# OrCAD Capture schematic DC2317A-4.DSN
size B; title: HIGH EFFICIENCY 4 PHASE 120A; rev: 4; company: TM
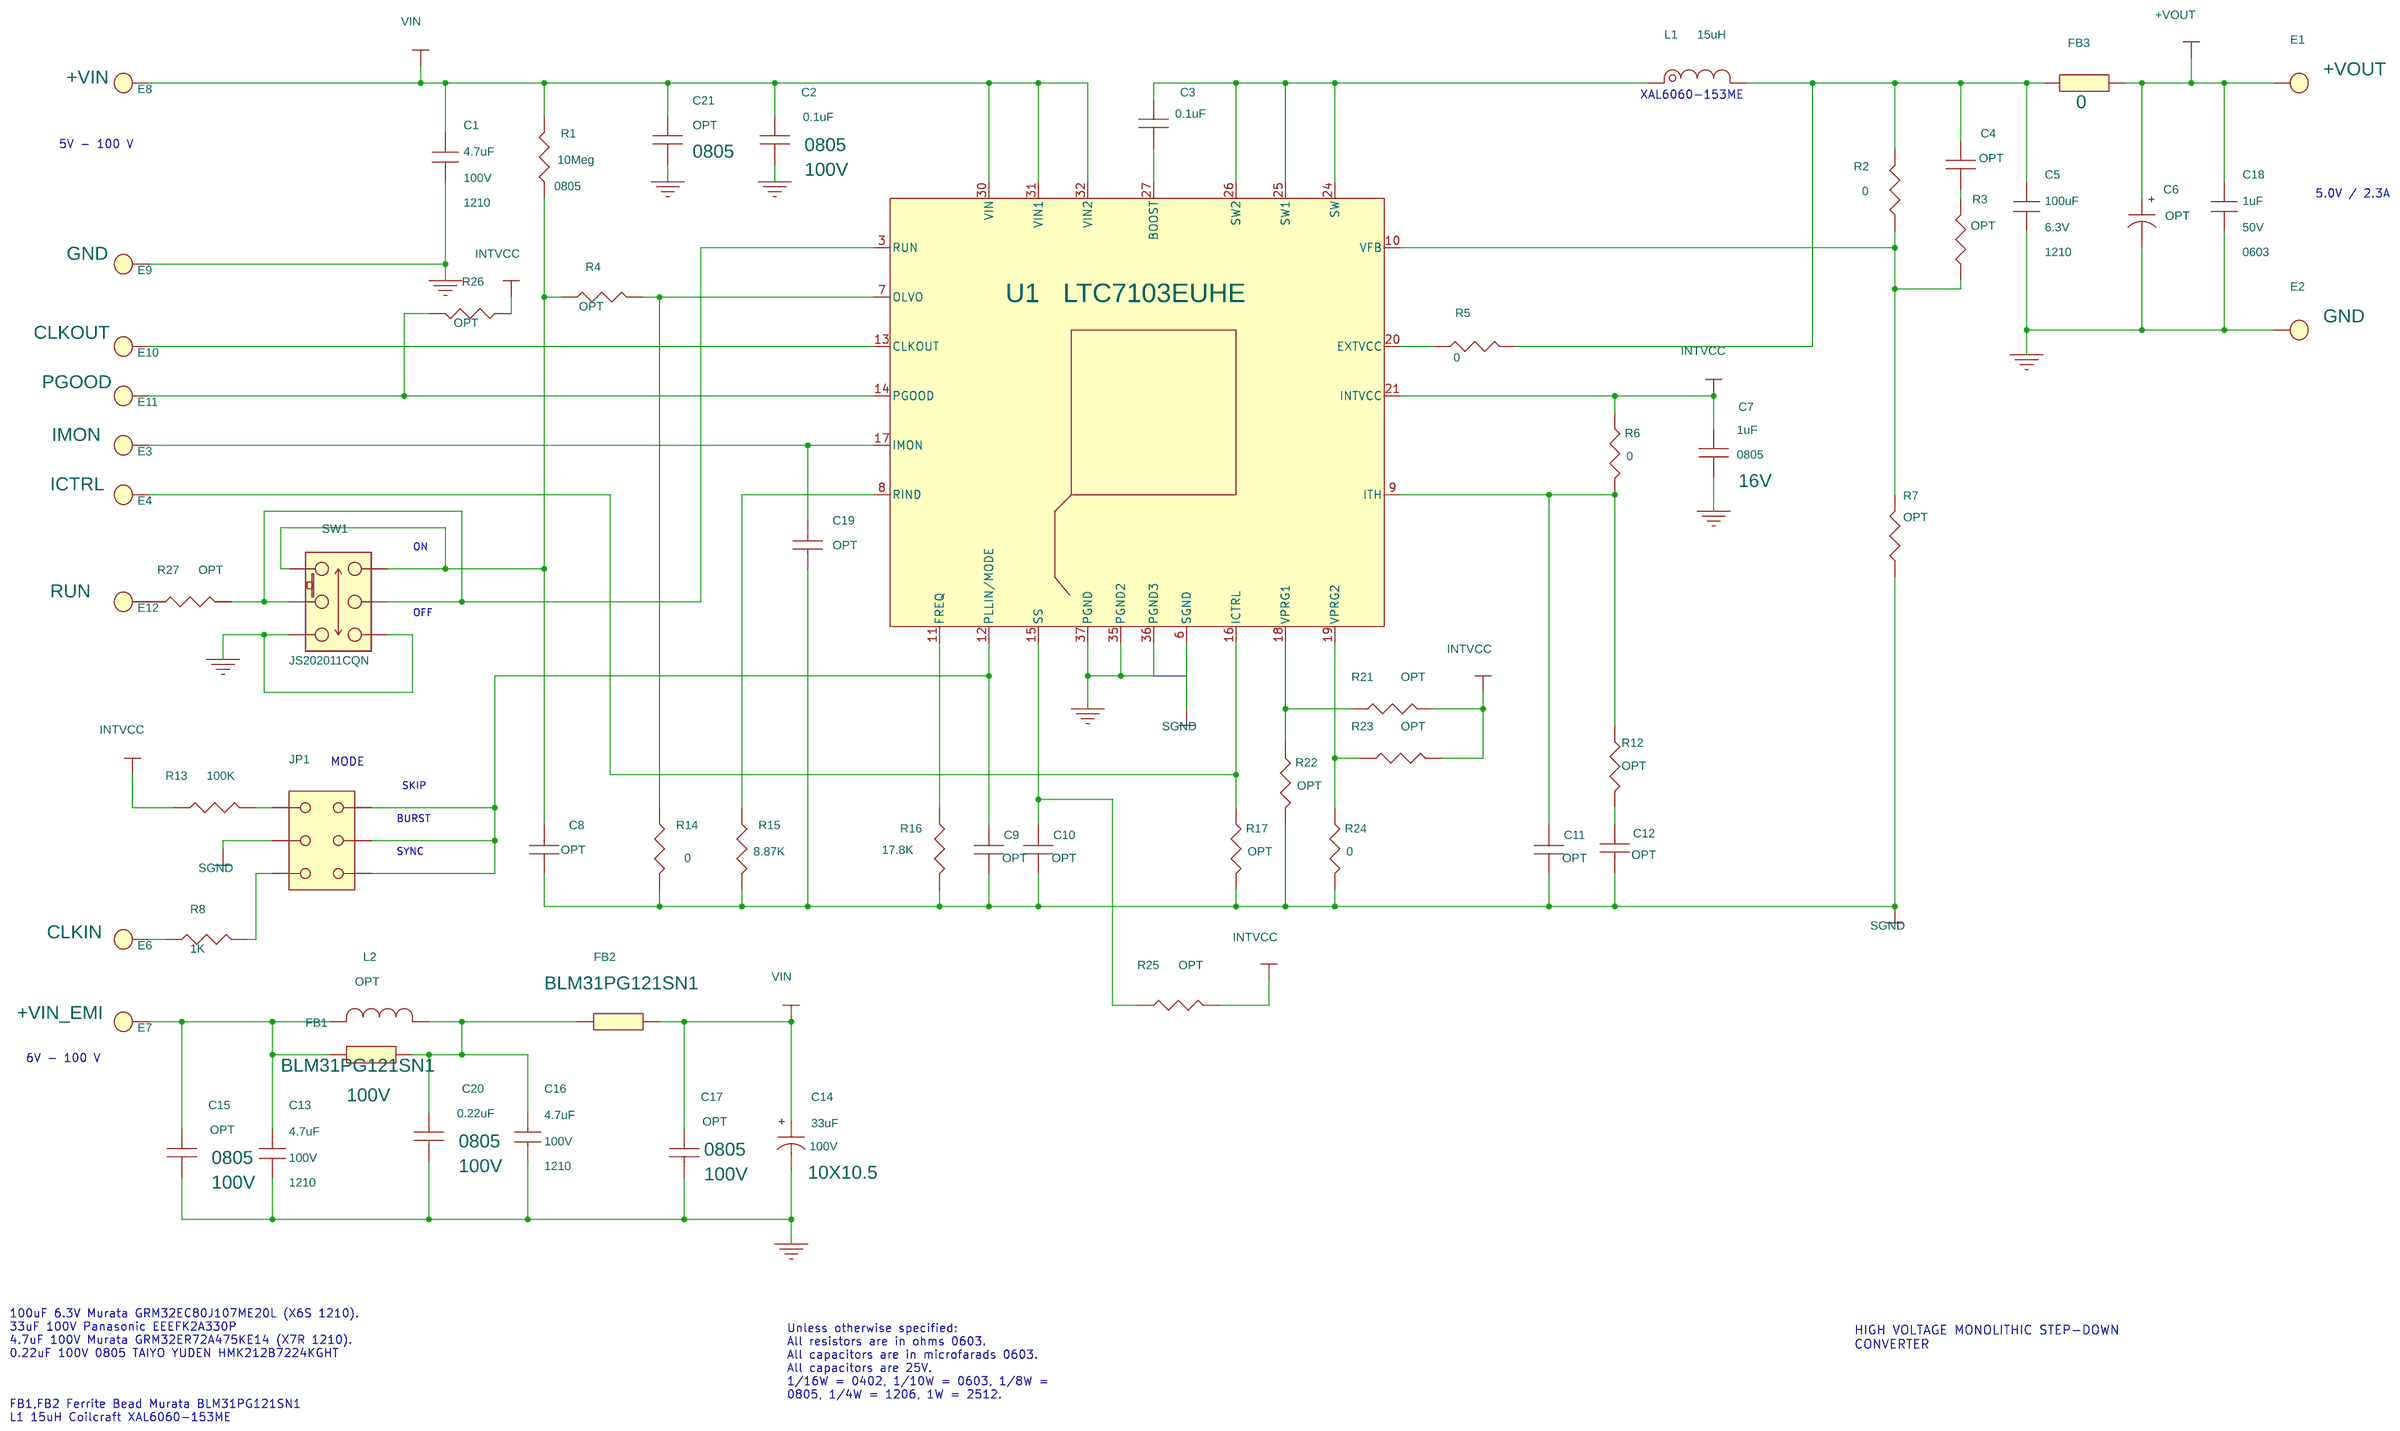
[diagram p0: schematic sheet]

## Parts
C1  4.7uF  [1210]
C2  0.1uF  [0805]
C3  0.1uF  [0603]
C4  OPT  [0603]
C5  100uF  [1210]
C6  OPT  [7343]
C7  1uF  [0805]
C8  OPT  [0805]
C9  OPT  [0603]
C10  OPT  [0603]
C11  OPT  [0603]
C12  OPT  [0603]
C13  4.7uF  [1210]
C14  33uF  [SANYO-10.3X10.3]
C15  OPT  [0805]
C16  4.7uF  [1210]
C17  OPT  [0805]
C18  1uF  [0603]
C19  OPT  [0603]
C20  0.22uF  [0805]
C21  OPT  [0805]
E1  TURRET-23  [pad150-095]
E2  TURRET-23  [pad150-095]
E3  TURRET-23  [pad150-095]
E4  TURRET-23  [pad150-095]
E6  TURRET-23  [pad150-095]
E7  TURRET-23  [pad150-095]
E8  TURRET-23  [pad150-095]
E9  TURRET-23  [pad150-095]
E10  TURRET-23  [pad150-095]
E11  TURRET-23  [pad150-095]
E12  TURRET-23  [pad150-095]
FB1  BLM31PG121SN1  [1206]
FB2  BLM31PG121SN1  [1206]
FB3  0  [1206]
JP1  Voltage Select  [JP2X3/079]
L1  15uH  [XAL6060]
L2  OPT  [IHLP-1616]
R1  10Meg  [0805]
R2  0  [0603]
R3  OPT  [0603]
R4  OPT  [0805]
R5  0  [0603]
R6  0  [0603]
R7  OPT  [0603]
R8  1K  [0603]
R12  OPT  [0603]
R13  100K  [0603]
R14  0  [0603]
R15  8.87K  [0603]
R16  17.8K  [0603]
R17  OPT  [0603]
R21  OPT  [0603]
R22  OPT  [0603]
R23  OPT  [0603]
R24  0  [0603]
R25  OPT  [0603]
R26  OPT  [0603]
R27  OPT  [0603]
SW1  JS202011CQN  [JS202011]
U1  LTC7103EUHE  [UHE_36_QFN_5MMX6MM]
XJP2  2mm Ctrs.

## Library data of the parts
C1 C13 C16 = CAP1210: 1ST PART FIELD: 100V; 2ND PART FIELD: 20%, 1210; 3RD PART FIELD: X7R; 4TH PART FIELD: TDK; 7TH PART FIELD: CAP.
C2 C15 C17 C20 C21 = 12061C104KAT2A_0: 1ST PART FIELD: 100V; 2ND PART FIELD: 10%, 0805; 3RD PART FIELD: X7R; 4TH PART FIELD: AVX; 7TH PART FIELD: CAP.
C3 = 12061C104KAT2A_0: 1ST PART FIELD: 25V; 2ND PART FIELD: 10%, 0805; 3RD PART FIELD: X7R; 4TH PART FIELD: AVX; 5TH PART FIELD: 0805; 7TH PART FIELD: CAP.
C4 = 12061C104KAT2A_0: 1ST PART FIELD: 25V; 2ND PART FIELD: 10%, 0603; 3RD PART FIELD: NPO; 4TH PART FIELD: AVX; 5TH PART FIELD: 06033A680KAT2A; 7TH PART FIELD: CAP.
C5 = CAP1210: 1ST PART FIELD: 6.3V; 2ND PART FIELD: 20%, 1210; 3RD PART FIELD: X7R; 4TH PART FIELD: TDK; 7TH PART FIELD: CAP.
C6 = CAP+7343: 1ST PART FIELD: 16V
C7 = TMK316BJ105KL: 1ST PART FIELD: 16V; 2ND PART FIELD: 10%, 0805; 3RD PART FIELD: X7R; 4TH PART FIELD: TAIYO TUDEN; 7TH PART FIELD: CAP.
C8-C11 C19 = 12061C104KAT2A_0: 1ST PART FIELD: 25V; 2ND PART FIELD: 10%, 0603; 3RD PART FIELD: NPO; 4TH PART FIELD: AVX; 5TH PART FIELD: 06033A471KAT2A; 7TH PART FIELD: CAP.
C12 = 12061C104KAT2A_0: 1ST PART FIELD: 25V; 2ND PART FIELD: 10%, 0603; 3RD PART FIELD: X7R; 4TH PART FIELD: AVX; 5TH PART FIELD: 06033C103KAT2A; 7TH PART FIELD: CAP.
C14 = CAP-HVH-10X10.5: 1ST PART FIELD: 100V; 5TH PART FIELD: 10X10.5
C18 = CAP1210: 1ST PART FIELD: 50V; 2ND PART FIELD: 20%, 1210; 3RD PART FIELD: X7R; 4TH PART FIELD: TDK; 5TH PART FIELD: 1210; 7TH PART FIELD: CAP.
E1 = TURRET_2501-2: 9TH PART FIELD: +VOUT
E2 E9 = TURRET_2501-2: 9TH PART FIELD: GND
E3 = TURRET_2501-2: 9TH PART FIELD: IMON
E4 = TURRET_2501-2: 9TH PART FIELD: ICTRL
E6 = TURRET_2501-2: 9TH PART FIELD: CLKIN
E7 = TURRET_2501-2: 9TH PART FIELD: +VIN_EMI
E8 = TURRET_2501-2: 9TH PART FIELD: +VIN
E10 = TURRET_2501-2: 9TH PART FIELD: CLKOUT
E11 = TURRET_2501-2: 9TH PART FIELD: PGOOD
E12 = TURRET_2501-2: 9TH PART FIELD: RUN
FB1 = FUSE_1: COMPFIXED: BLM31PG391SN1; COMPGROUP: MURATA; value2: 100V
FB2 = FUSE_1: COMPFIXED: BLM31PG391SN1; COMPGROUP: MURATA
FB3 = FUSE_1: COMPFIXED: BLM31PG391SN1; COMPGROUP: MURATA; COMPKEY: BLM31PG121SN1
JP1 = CON6AP_0
L1 = IND-PA1382_11.650: 4TH PART FIELD: PULSE,
L2 = IND-IHLP-2525CZ-01: 4TH PART FIELD: IHLP2020BZER4R&M01
R1 = AAC-0805: 2ND PART FIELD: 1%, 0805; 7TH PART FIELD: RES.
R2-R8 R13-R17 R21-R27 = AAC-0805: 1ST PART FIELD: 1/16W; 2ND PART FIELD: 1%, 0603; 5TH PART FIELD: CR16-xxxxFM; 7TH PART FIELD: RES.
R12 = CR10-203JM_0: 1ST PART FIELD: 1/16W; 2ND PART FIELD: 5%, 0603; 3RD PART FIELD: CHIP; 4TH PART FIELD: AAC; 5TH PART FIELD: CR16-xxxJM; 7TH PART FIELD: RES.
SW1 = SW_3: HEADER, 4PIN, DBL ROW 2mm
U1 = LTC1629_24: IC, DUAL OUTPUT BUCK CONTROLLER; Part Number: LINEAR TECH. LTC3860EUH
XJP2 = Samtec_2SN-BK-G: SHUNT; Part Number: SAMTEC 2SN-BK-G

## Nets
GND: C1.2 C2.1 C5.2 C6.2 C7.2 C13.2 C14.2 C15.1 C16.2 C17.1 C18.2 C20.1 C21.1 E2.1 E9.1 SW1.3 SW1.6 U1.35(PGND2) U1.36(PGND3) U1.37(PGND)
SGND: C8.2 C9.2 C10.2 C11.2 C12.1 C19.2 JP1.3 R7.1 R14.2 R15.2 R16.2 R17.2 R22.2 R24.2 U1.6(SGND)
VIN: C1.1 C2.2 C14.1 C17.2 C21.2 E8.1 FB2.2 R1.1 U1.30(VIN) U1.31(VIN1) U1.32(VIN2)
+VOUT: C6.1 C18.1 E1.1 FB3.2
INTVCC: C7.1 R6.1 R13.1 R21.2 R23.2 R25.2 R26.1 U1.21(INTVCC)
N18866994: R27.2 SW1.2 SW1.5 U1.3(RUN)
N18867008: C8.1 R1.2 R4.1 SW1.1 SW1.4
N18867022: C9.1 JP1.2 JP1.4 JP1.6 U1.12(PLLIN/MODE)
N18867071: C4.2 C5.1 FB3.1 L1.1 R2.2 R5.2
N18867073: R2.1 R3.1 R7.2 U1.10(VFB)
N18867075: C12.2 R12.1
N18867125: E4.1 R17.1 U1.16(ICTRL)
N18867165: C16.1 C20.2 FB1.2 FB2.1 L2.2
N18867189: C4.1 R3.2
N18867191: C3.2 L1.2 U1.24(SW) U1.25(SW1) U1.26(SW2)
N18867233: C3.1 U1.27(BOOST)
N18867243: R16.1 U1.11(FREQ)
N18867333: E11.1 R26.2 U1.14(PGOOD)
N18867359: R15.1 U1.8(RIND)
N18867383: R21.1 R22.1 U1.18(VPRG1)
N18867407: E10.1 U1.13(CLKOUT)
N18867455: R5.1 U1.20(EXTVCC)
N18867465: R4.2 R14.1 U1.7(OLVO)
N18867469: C11.1 R6.2 R12.2 U1.9(ITH)
N18867626: C10.1 R25.1 U1.15(SS)
N18867660: C19.1 E3.1 U1.17(IMON)
N18867683: R23.1 R24.1 U1.19(VPRG2)
N18867687: E6.1 R8.1
N18867801: JP1.1 R13.2
N18867825: JP1.5 R8.2
N18867980: C13.1 C15.2 E7.1 FB1.1 L2.1
N18881459: E12.1 R27.1

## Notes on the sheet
- XAL6060-153ME
- 5V - 100 V
- 5.0V / 2.3A
- ON
- OFF
- MODE
- SKIP
- BURST
- SYNC
- 6V - 100 V
- 100uF 6.3V Murata GRM32EC80J107ME20L (X6S 1210).
  33uF 100V Panasonic EEEFK2A330P
  4.7uF 100V Murata GRM32ER72A475KE14 (X7R 1210).
  0.22uF 100V 0805 TAIYO YUDEN HMK212B7224KGHT
- Unless otherwise specified:
  All resistors are in ohms 0603.
  All capacitors are in microfarads 0603.
  All capacitors are 25V.
  1/16W = 0402, 1/10W = 0603, 1/8W =
  0805, 1/4W = 1206, 1W = 2512.
- HIGH VOLTAGE MONOLITHIC STEP-DOWN
  CONVERTER
- FB1,FB2 Ferrite Bead Murata BLM31PG121SN1
  L1 15uH Coilcraft XAL6060-153ME
